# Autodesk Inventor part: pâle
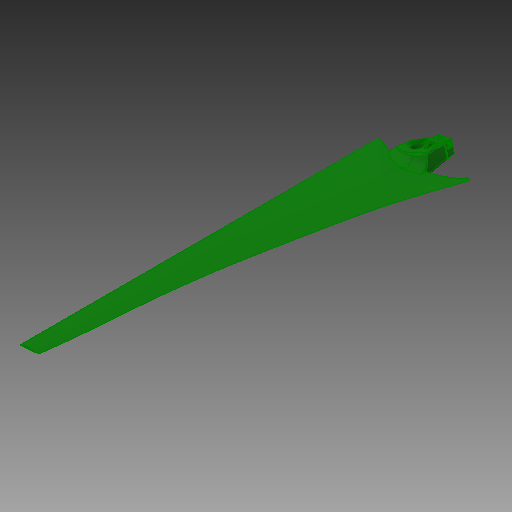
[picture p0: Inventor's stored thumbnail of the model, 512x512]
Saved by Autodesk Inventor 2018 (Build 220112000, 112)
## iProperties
Created: 2009-05
Part Number: pâle
Material: Générique
Document SubType Name: Modeling
Designer: TJ
Density: 1 g/cm^3
Appearance: Par défaut
Author: TJ
Sending System: SolidWorks 2008
Last Author: Roger
Last Saved: 2011-02-17
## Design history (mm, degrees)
extrude "Extrusion4"
node "Solide1"
